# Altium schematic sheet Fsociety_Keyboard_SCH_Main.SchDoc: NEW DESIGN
size A2; CompanyName: Rena Electronica; Engineer: IK; Organization: Rena Electronica; Address1: de Ambachten 12; Address2: 4881 XZ; Address3: Zundert; Address4: the Netherlands; DocumentNumber: 05.xxx; Revision: 0.10; Customer: Klantnaam; PageSetup: Record=PageOptions¦CenterHorizontal=True¦CenterVertical=True¦PrintScale=0.73¦XCorrection=1.00¦YCorrection=1.00¦PrintKind=0¦BorderSize=5000000¦LeftOffset=0¦BottomOffset=0¦Orientation=2¦PaperLength=1000¦PaperWidth=1000¦Scale=100¦PaperSource=7¦PrintQuality=-3¦MediaType=1¦DitherType=10¦PrintScaleMode=1¦PaperKind=A3¦PaperIndex=8
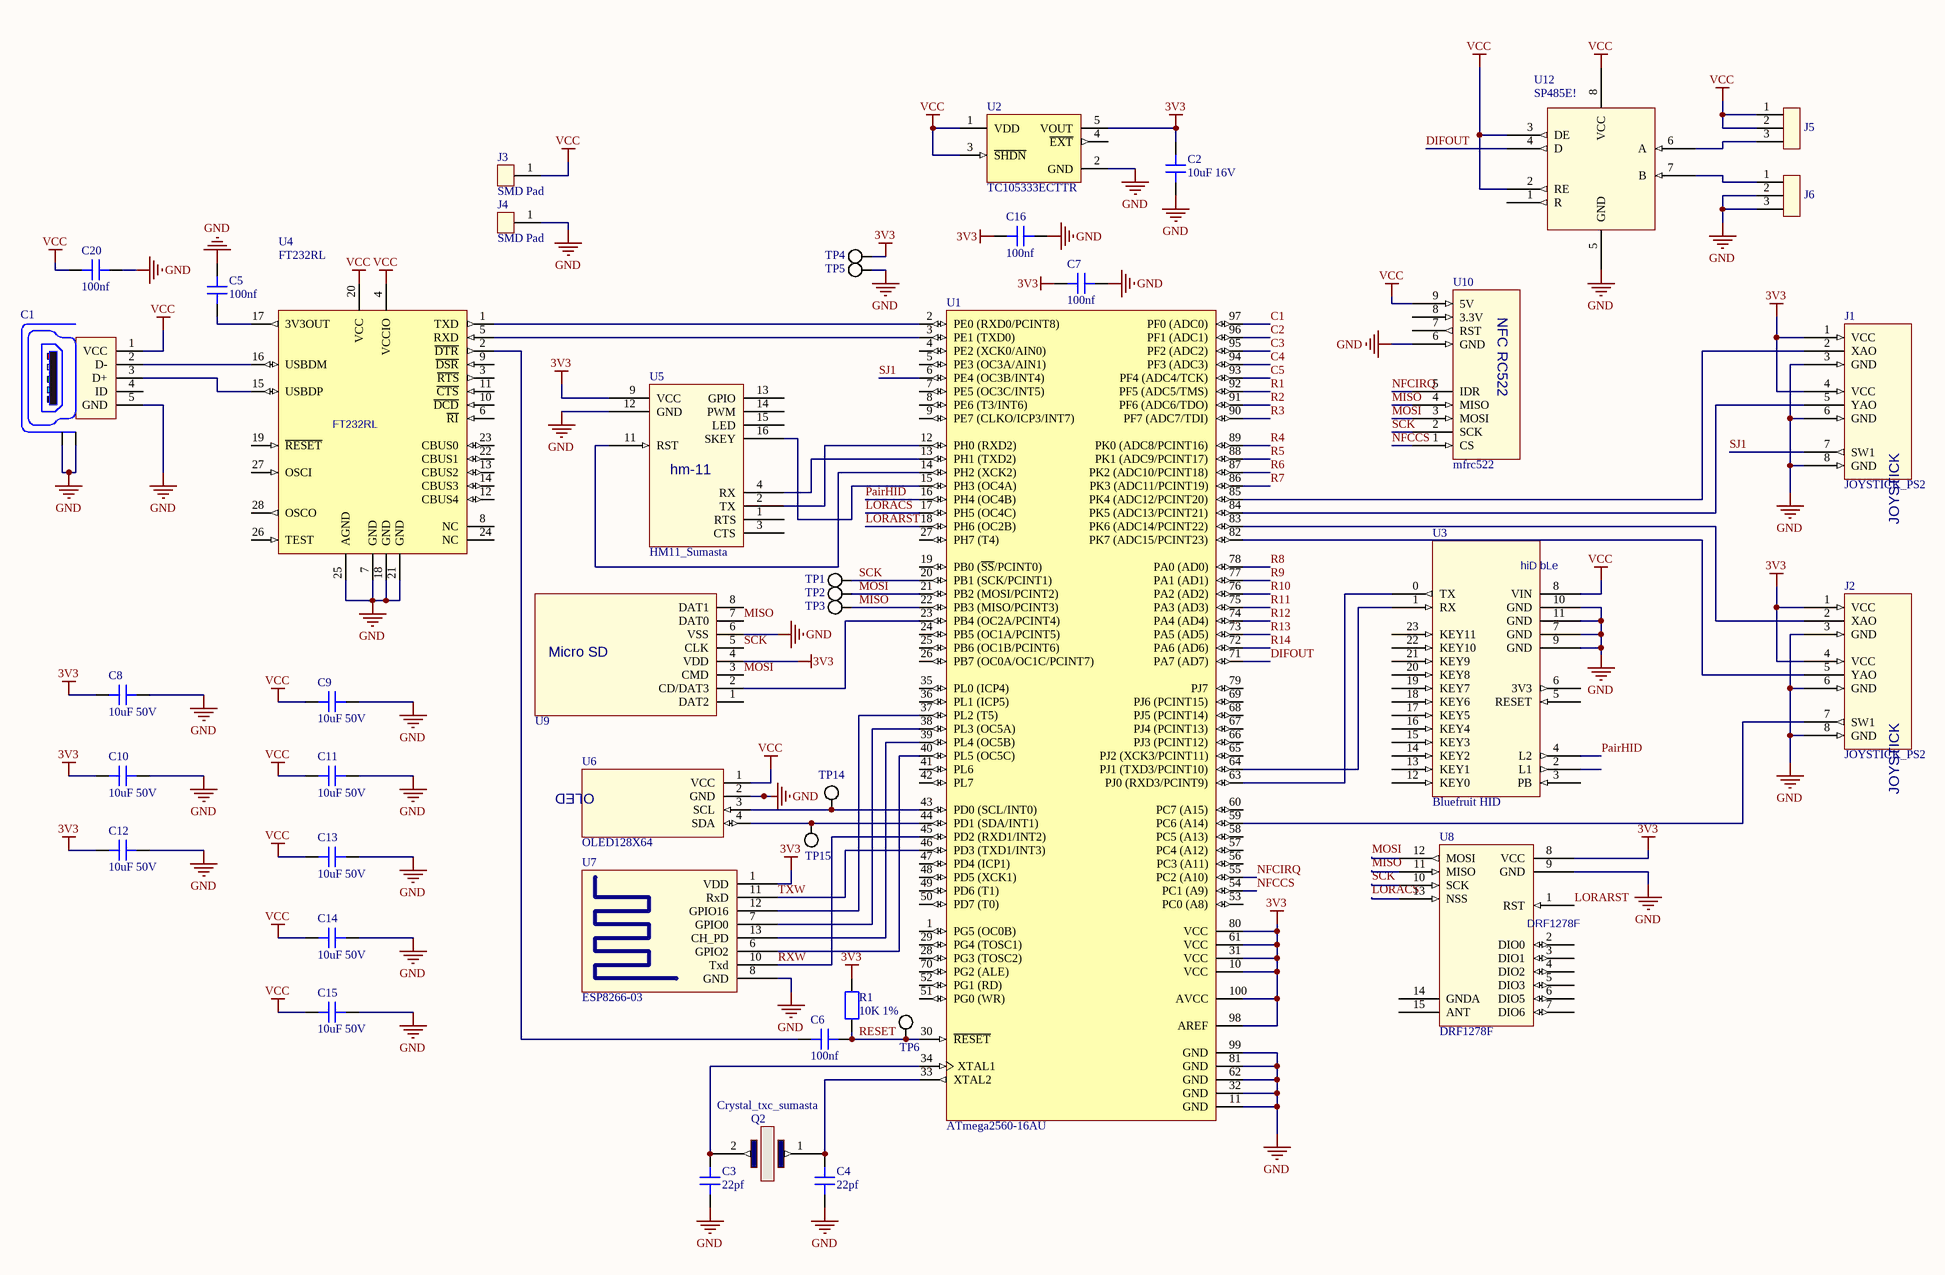
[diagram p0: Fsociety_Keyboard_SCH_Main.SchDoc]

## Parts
C1  WR-Communication Connectors 629105150921  [629105150921]  (value not drawn)
C2  10uF 16V  [CAPC1608X08_NR]
C3  22pf  [CAPC1608X08_NR]
C4  22pf  [CAPC1608X08_NR]
C5  100nf  [CAPC1608X08_NR]
C6  100nf  [CAPC1608X08_NR]
C7  100nf  [CAPC1608X08_NR]
C8  10uF 50V  [CAPC3216X09_MW]
C9  10uF 50V  [CAPC3216X09_MW]
C10  10uF 50V  [CAPC3216X09_MW]
C11  10uF 50V  [CAPC3216X09_MW]
C12  10uF 50V  [CAPC3216X09_MW]
C13  10uF 50V  [CAPC3216X09_MW]
C14  10uF 50V  [CAPC3216X09_MW]
C15  10uF 50V  [CAPC3216X09_MW]
C16  100nf  [CAPC1608X08_NR]
C20  100nf  [CAPC1608X08_NR]
J1  JOYSTICK_PS2  [JOYSTICK]
J2  JOYSTICK_PS2  [JOYSTICK]
J3  SMD Pad  [CON_SMDPAD_10X5]  (no BOM)
J4  SMD Pad  [CON_SMDPAD_10X5]  (no BOM)
J5  BB02-HA031-KB1-100/33/D1  [FCI_77315-134-03LF]  (value not drawn)
J6  BB02-HA031-KB1-100/33/D1  [FCI_77315-134-03LF]  (value not drawn)
Q2  Crystal_txc_sumasta  [Crystal_txc_sumasta]
R1  10K 1%  [RESC1608X06_NR]
TP1  TP  [TESTPAD-2MM]  (value not drawn)  (no BOM)
TP2  TP  [TESTPAD-2MM]  (value not drawn)  (no BOM)
TP3  TP  [TESTPAD-2MM]  (value not drawn)  (no BOM)
TP4  TP  [TESTPAD-2MM]  (value not drawn)  (no BOM)
TP5  TP  [TESTPAD-2MM]  (value not drawn)  (no BOM)
TP6  TP  [TESTPAD-2MM]  (value not drawn)  (no BOM)
TP14  TP  [TESTPAD-2MM]  (value not drawn)  (no BOM)
TP15  TP  [TESTPAD-2MM]  (value not drawn)  (no BOM)
U1  ATmega2560-16AU  [100A_N]
U2  TC105333ECTTR  [SOT-23-CT5_N]
U3  Bluefruit HID  [BLuefruit HID]
U4  FT232RL  [SSPO28]
U5  HM11_Sumasta  [HM11_Sumasta]
U6  OLED128X64  [OLED128x64]
U7  ESP8266-03  [ESP8266-03]
U8  DRF1278F  [DRF1278F]
U9  Micro SD Connector - Hinge  [Micro SD Socket]  (value not drawn)
U10  mfrc522  [MFRC522]
U12  MAXPartNumber: SP485E!  [SOIC127P600-8N]  (hidden comment: RS485 Buffer Transceiver)

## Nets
3V3: C2.2 C7.1 C8.1 C10.1 C12.1 C16.1 J1.1(VCC) J1.4(VCC) J2.1(VCC) J2.4(VCC) R1.2 TP4.1 U1.10(VCC) U1.31(VCC) U1.61(VCC) U1.80(VCC) U1.98(AREF) U1.100(AVCC) U2.5(VOUT) U5.9(VCC) U7.1(VDD) U8.8(VCC) U9.4(VDD)
GND: C1.5(GND) C1.Z1(Shield) C1.Z2(Shield) C2.1 C3.1 C4.1 C5.2 C7.2 C8.2 C9.2 C10.2 C11.2 C12.2 C13.2 C14.2 C15.2 C16.2 C20.1 J1.3(GND) J1.6(GND) J1.8(GND) J2.3(GND) J2.6(GND) J2.8(GND) J4.1 J6.2 J6.3 TP5.1 U1.11(GND) U1.32(GND) U1.62(GND) U1.81(GND) U1.99(GND) U2.2(GND) U3.7(GND) U3.9(GND) U3.10(GND) U3.11(GND) U4.7(GND) U4.18(GND) U4.21(GND) U4.25(AGND) U5.12(GND) U6.2(GND) U7.8(GND) U8.9(GND) U9.6(VSS) U10.6(GND) U12.5(GND)
VCC: C1.1(VCC) C9.1 C11.1 C13.1 C14.1 C15.1 C20.2 J3.1 J5.1 J5.2 U2.1(VDD) U2.3(~{SHDN}) U3.8(VIN) U4.4(VCCIO) U4.20(VCC) U6.1(VCC) U10.9(5V) U12.2(RE) U12.3(DE) U12.8(VCC)
C1: U1.97(PF0_(ADC0))
C2: U1.96(PF1_(ADC1))
C3: U1.95(PF2_(ADC2))
C4: U1.94(PF3_(ADC3))
C5: U1.93(PF4_(ADC4/TCK))
DIFOUT: U1.71(PA7_(AD7)) U12.4(D)
LORACS: U1.17(PH5_(OC4C)) U8.13(NSS)
LORARST: U1.18(PH6_(OC2B)) U8.1(RST)
MISO: TP3.1 U1.22(PB3_(MISO/PCINT3)) U8.11(MISO) U9.7(DAT0) U10.4(MISO)
MOSI: TP2.1 U1.21(PB2_(MOSI/PCINT2)) U8.12(MOSI) U9.3(CMD) U10.3(MOSI)
NFCCS: U1.54(PC1_(A9)) U10.1(CS)
NFCIRQ: U1.55(PC2_(A10)) U10.5(IDR)
PairHID: U1.16(PH4_(OC4B)) U3.4(L2)
R1: U1.92(PF5_(ADC5/TMS))
R2: U1.91(PF6_(ADC6/TDO))
R3: U1.90(PF7_(ADC7/TDI))
R4: U1.89(PK0_(ADC8/PCINT16))
R5: U1.88(PK1_(ADC9/PCINT17))
R6: U1.87(PK2_(ADC10/PCINT18))
R7: U1.86(PK3_(ADC11/PCINT19))
R8: U1.78(PA0_(AD0))
R9: U1.77(PA1_(AD1))
R10: U1.76(PA2_(AD2))
R11: U1.75(PA3_(AD3))
R12: U1.74(PA4_(AD4))
R13: U1.73(PA5_(AD5))
R14: U1.72(PA6_(AD6))
RESET: C6.2 R1.1 TP6.1 U1.30(~{RESET})
RXW: U1.45(PD2_(RXD1/INT2)) U7.10(Txd)
SCK: TP1.1 U1.20(PB1_(SCK/PCINT1)) U8.10(SCK) U9.5(CLK) U10.2(SCK)
SJ1: J1.7(SW1) U1.6(PE4_(OC3B/INT4))
TXW: U1.46(PD3_(TXD1/INT3)) U7.11(RxD)
NetC1_2: C1.2(D-) U4.16(USBDM)
NetC1_3: C1.3(D+) U4.15(USBDP)
NetC3_2: C3.2 Q2.2 U1.34(XTAL1)
NetC4_2: C4.2 Q2.1 U1.33(XTAL2)
NetC5_1: C5.1 U4.17(3V3OUT)
NetC6_1: C6.1 U4.2(~{DTR})
NetJ1_2: J1.2(XAO) U1.85(PK4_(ADC12/PCINT20))
NetJ1_5: J1.5(YAO) U1.84(PK5_(ADC13/PCINT21))
NetJ2_2: J2.2(XAO) U1.83(PK6_(ADC14/PCINT22))
NetJ2_5: J2.5(YAO) U1.82(PK7_(ADC15/PCINT23))
NetJ2_7: J2.7(SW1) U1.59(PC6_(A14))
NetJ5_3: J5.3 U12.6(A)
NetJ6_1: J6.1 U12.7(B)
NetTP14_1: TP14.1 U1.43(PD0_(SCL/INT0)) U6.3(SCL)
NetTP15_1: TP15.1 U1.44(PD1_(SDA/INT1)) U6.4(SDA)
NetU1_2: U1.2(PE0_(RXD0/PCINT8)) U4.1(TXD)
NetU1_3: U1.3(PE1_(TXD0)) U4.5(RXD)
NetU1_12: U1.12(PH0_(RXD2)) U5.2(TX)
NetU1_13: U1.13(PH1_(TXD2)) U5.4(RX)
NetU1_14: U1.14(PH2_(XCK2)) U5.11(RST)
NetU1_15: U1.15(PH3_(OC4A)) U5.16(SKEY)
NetU1_23: U1.23(PB4_(OC2A/PCINT4)) U9.2(CD/DAT3)
NetU1_37: U1.37(PL2_(T5)) U7.12(GPIO16)
NetU1_38: U1.38(PL3_(OC5A)) U7.7(GPIO0)
NetU1_39: U1.39(PL4_(OC5B)) U7.13(CH_PD)
NetU1_40: U1.40(PL5_(OC5C)) U7.6(GPIO2)
NetU1_63: U1.63(PJ0_(RXD3/PCINT9)) U3.0(TX)
NetU1_64: U1.64(PJ1_(TXD3/PCINT10)) U3.1(RX)

Not connected (* = marked no-connect by the designer): C1 4(ID); U1 1(PG5_(OC0B)) 4(PE2_(XCK0/AIN0)) 5(PE3_(OC3A/AIN1)) 7(PE5_(OC3C/INT5)) 8(PE6_(T3/INT6)) 9(PE7_(CLKO/ICP3/INT7)) 19(PB0_(~{SS}/PCINT0)) 24(PB5_(OC1A/PCINT5)) 25(PB6_(OC1B/PCINT6)) 26(PB7_(OC0A/OC1C/PCINT7)) 27(PH7_(T4)) 28(PG3_(TOSC2)) 29(PG4_(TOSC1)) 35(PL0_(ICP4)) 36(PL1_(ICP5)) 41(PL6) 42(PL7) 47(PD4_(ICP1)) 48(PD5_(XCK1)) 49(PD6_(T1)) 50(PD7_(T0)) 51(PG0_(WR)) 52(PG1_(RD)) 53(PC0_(A8)) 56(PC3_(A11)) 57(PC4_(A12)) 58(PC5_(A13)) 60(PC7_(A15)) 65(PJ2_(XCK3/PCINT11)) 66(PJ3_(PCINT12)) 67(PJ4_(PCINT13)) 68(PJ5_(PCINT14)) 69(PJ6_(PCINT15)) 70(PG2_(ALE)) 79(PJ7); U2 4(~{EXT}); U3 2(L1) 3(PB) 5(RESET) 6(3V3) 12(KEY0) 13(KEY1) 14(KEY2) 15(KEY3) 16(KEY4) 17(KEY5) 18(KEY6) 19(KEY7) 20(KEY8) 21(KEY9) 22(KEY10) 23(KEY11); U4 3(~{RTS}) 6(~{RI}) 8(NC) 9(~{DSR}) 10(~{DCD}) 11(~{CTS}) 12(CBUS4) 13(CBUS2) 14(CBUS3) 19(~{RESET}) 22(CBUS1) 23(CBUS0) 24(NC) 26(TEST) 27(OSCI) 28(OSCO); U5 1(RTS) 3(CTS) 13(GPIO) 14(PWM) 15(LED); U8 2(DIO0) 3(DIO1) 4(DIO2) 5(DIO3) 6(DIO5) 7(DIO6) 14(GNDA) 15(ANT); U9 1(DAT2) 8(DAT1); U10 7(RST) 8(3.3V); U12 1(R)

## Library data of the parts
C1 = WR-Communication Connectors 629105150921: WR-COM_USB_Micro Type AB_Horizontal_SMT; Manufacturer: Würth Elektronik eiSos GmbH; ComponentLink1 Description: Manufacturer; ComponentLink2 Description: Datasheet; NoPins: 5
C2-C7 C16 C20 = CMP-00064-A.5: Capacitor 10nF X7R ±10% 50V 0603(1608) SMD; MAXPartNumber: 10N/50-0603!; Case-EIA: 0603; Case-Metric: 1608
C8-C15 = CMP-01312-A.1: Capacitor 10uF X5R ±20% 50V 1206(3216) SMD; MAXPartNumber: 10U/50!; Case-Metric: 3216; Case-EIA: 1206
J3 J4 = CMP-00667-A.10: SMD PAD DIFFERENT SHAPES; MAXPartNumber: PAD_SMD!#
J5 J6 = CMP-01396-A.1: Unshrouded header 3-pin right angle; FLS_PN: CON-BB02-HA031
R1 = CMP-00060-A.4: 10K  0.1W 1% 0603(1608 Metric) SMD; MaxPartNumber: 10K-0603!; Case-EIA: 0603; Case-Metric: 1608; Value: 10K Ohm
TP1-TP6 TP14 TP15 = CMP-00759-A.11: TESTPOINT; FLS_PN: TP#
U1 = ATmega2560-16AU: 8-bit AVR Microcontroller, 4.5-5.5V, 16MHz, 256KB Flash, 4KB EEPROM, 8KB SRAM, 86 GPIO pins, 100-pin TQFP, Industrial Grade (-40°C to 85°C), Pb-Free
U2 = TC105333ECTTR: PFM/PWM Step-Down DC/DC Controller, 1A, 3.3V, 300kHz, 5-Pin SOT-23, Industrial Temperature, Tape and Reel; Manufacturer: Microchip
U9 = MicroSD Socket
U12 = SN75176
